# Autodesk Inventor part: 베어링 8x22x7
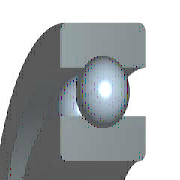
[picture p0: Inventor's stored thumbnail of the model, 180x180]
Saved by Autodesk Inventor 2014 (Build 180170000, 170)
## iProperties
IsCustomPart: 1
Created: 2012-02
Part Number: 베어링 8x22x7
Material: 강철, 연강
Description: 깊은 그루브 볼 베어링
Document SubType Name: Modeling
Standard: KS B 2023
Designer: mduedu
Standards Organization: KS
Language: ko-KR
Size Designation: 608 - 8 x 22 x 7
Categories: <MemberInstance><Categories><Category DisplayName="샤프트 부품" InternalName="7f7aeb1f-a693-4053-b835-cee3144e0d98" Mnemonic="SHFT"><Category DisplayName="베어링" Inter
Density: 1 g/cm^3
Appearance: 노란색
Author: mduedu
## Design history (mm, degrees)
sketch "스케치" dims "d0" = 3.64 (= -0.26 x WD + 0.26 x BD)
  geometry: L1 (1.68, 7.5)-(5.32, 7.5); L2 (3.5, 7.5)-(3.5, 5.68); L3 (3.5, 7.5)-(3.5, 9.32); L4 (2.148, 6.282)-(0, 6.282); L5 (0, 4)-(7, 4); L6 (2.148, 8.718)-(0, 8.718); L7 (0, 11)-(7, 11); L8 (7, 4)-(7, 6.282); L9 (4.852, 6.282)-(7, 6.282); L10 (4.852, 8.718)-(7, 8.718); L11 (7, 11)-(7, 8.718); L12 (-1.4, 0)-(8.4, 0) reference; L13 (0, -0.3)-(0, 5.3) reference
  constraints: 22 end point, 4 point on line, 2 collinear, 2 perpendicular, 2 symmetric about line, 1 midpoint, 1 parallel, 14 other
  dimensions: "d9" = 8 diameter of L5 L12 (= WD); "d11" = 22 diameter of L7 L12 (= BD); "d12" = 7 distance between parallel lines of L8 L13 (= KB); "d13" = 12.564 diameter of L9 L12 (= 0.326 x BD + 0.674 x WD)
revolve "본체" stored, may be unused: angle "d6" = 90 deg
revolve "볼" stored, may be unused: angle "d7" = 90 deg
pattern_circular "IDS_ARRAYBALL[SIMPL:T]" dims angle "d3" = 360 deg
body "Solid1"
fillet "모깎기1" dims "d1" = 0.3 (= KRS)
other parameters: "WD" = 8 [user parameter; used in 5 equation terms], "BD" = 22 [user parameter; used in 5 equation terms], "KB" = 7 [user parameter; used in 1 equation term], "KRS" = 0.3 [user parameter; used in 1 equation term], "d4" = 0, "d5" = 0, "d8" = 0, "d14" = 0, "d15" = 0, "BBA" = 0 [user parameter], "BC0" = 1370000 [user parameter], "BC" = 3250000 [user parameter], "BR" = 11 (= 0.5 x BD) [user parameter], "WR" = 4 (= 0.5 x WD) [user parameter]
